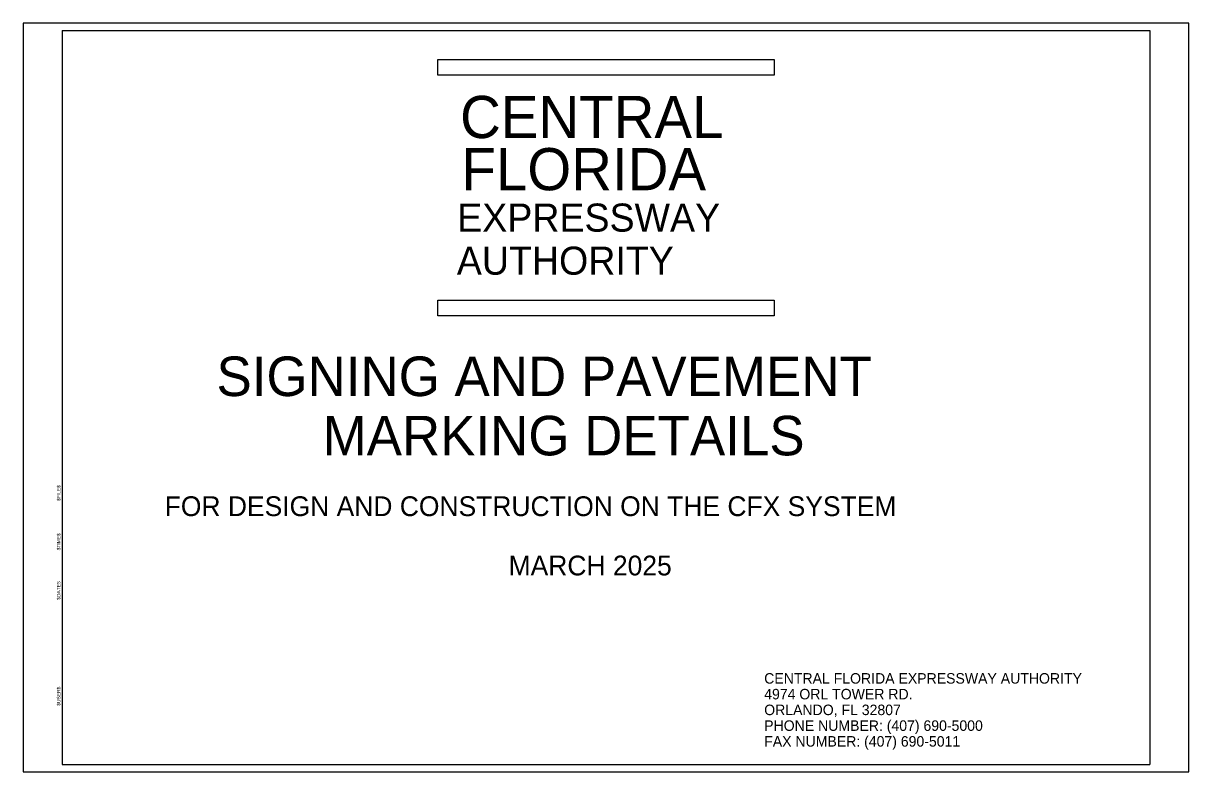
# Model space of a CAD drawing. Extents: x 1888.7 to 1905.2, y -90 to -79.4.
import ezdxf

# ---------------------------------------------------------------- set-up
doc = ezdxf.new("R2010")
doc.units = 0
for name, color, linetype in [('PlotBorder_dp', 7, 'Continuous'), ('SheetBorder_dp', 7, 'Continuous'), ('SignPanel', 7, 'Continuous'), ('TextLabel', 7, 'Continuous'), ('TextMisc', 7, 'Continuous'), ('TextStructures', 7, 'Continuous')]:
    doc.layers.add(name, color=color, linetype=linetype)

msp = doc.modelspace()

# ---------------------------------------------------------------- linework, layer by layer
at = {"layer": 'PlotBorder_dp'}
msp.add_lwpolyline([(1888.731, -90), (1905.231, -90), (1905.231, -79.4), (1888.731, -79.4)], close=True, dxfattribs=at)
at = {"layer": 'SheetBorder_dp'}
for p, q in [((1889.281, -79.5), (1889.281, -89.9)), ((1889.281, -79.5), (1904.681, -79.5)), ((1904.681, -79.5), (1904.681, -89.9)), ((1889.281, -89.9), (1904.681, -89.9))]:
    msp.add_line(p, q, dxfattribs=at)
at = {"layer": 'SignPanel'}
for points in [[(1894.598, -79.914), (1899.364, -79.914), (1899.364, -80.137), (1894.598, -80.137)], [(1894.598, -83.32), (1899.364, -83.32), (1899.364, -83.543), (1894.598, -83.543)]]:
    msp.add_lwpolyline(points, close=True, dxfattribs=at)

# ---------------------------------------------------------------- texts
for s, height, p in [('CENTRAL', 0.5974, (1894.915, -81.026)), ('FLORIDA', 0.5974, (1894.935, -81.765)), ('EXPRESSWAY', 0.3976, (1894.874, -82.351)), ('AUTHORITY', 0.3976, (1894.869, -82.961))]:
    msp.add_text(s, height=height, dxfattribs=at).set_placement(p)
at = {"layer": 'TextLabel'}
for s, p in [('SIGNING AND PAVEMENT', (1891.466, -84.68)), ('MARKING DETAILS', (1892.969, -85.52))]:
    msp.add_text(s, height=0.56, dxfattribs=at).set_placement(p)
at = {"layer": 'TextMisc'}
for s, p in [('$FILE$', (1889.256, -86.165)), ('$TIME$', (1889.256, -86.865)), ('$DATE$', (1889.256, -87.565)), ('$USER$', (1889.256, -89.065))]:
    msp.add_text(s, height=0.05, rotation=90, dxfattribs=at).set_placement(p)
at = {"layer": 'TextStructures'}
for s, height, p in [('FOR DESIGN AND CONSTRUCTION ON THE CFX SYSTEM', 0.28, (1890.733, -86.38)), ('MARCH 2025', 0.28, (1895.602, -87.22)), ('CENTRAL FLORIDA EXPRESSWAY AUTHORITY', 0.14875, (1899.221, -88.753)), ('4974 ORL TOWER RD.', 0.14875, (1899.221, -88.976)), ('ORLANDO, FL 32807', 0.14875, (1899.221, -89.199)), ('PHONE NUMBER: (407) 690-5000', 0.14875, (1899.221, -89.422)), ('FAX NUMBER: (407) 690-5011', 0.14875, (1899.221, -89.645))]:
    msp.add_text(s, height=height, dxfattribs=at).set_placement(p)

doc.saveas('drawing.dxf')
